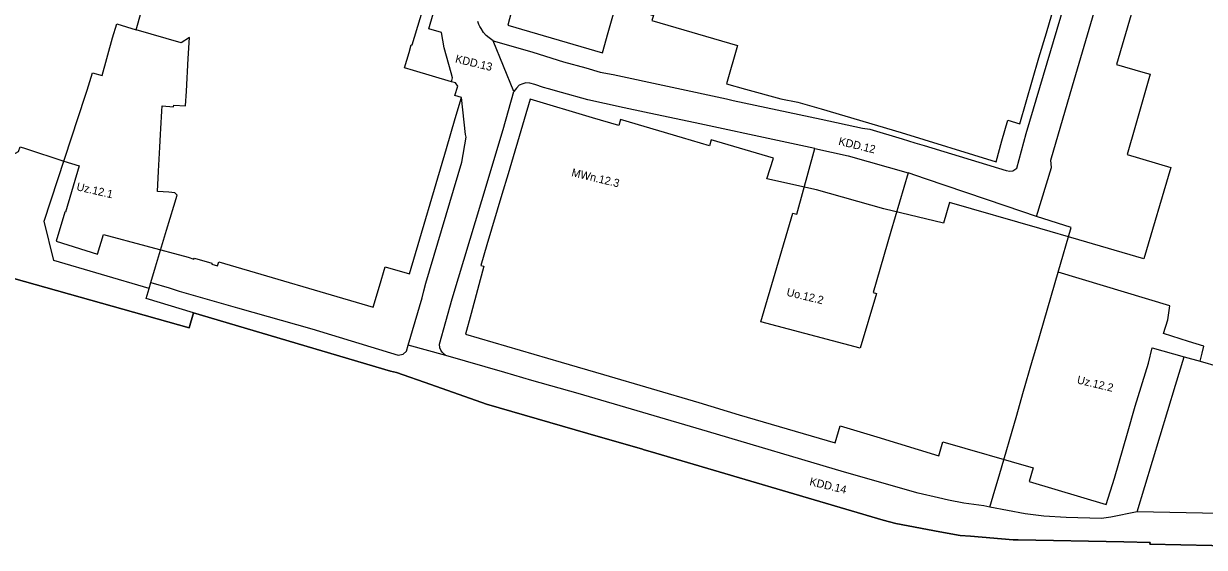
# Model space of a CAD drawing. Extents: x 7429686 to 7432896, y 5547954 to 5550600.
# Drawn here: x 7431434 to 7432024, y 5548197 to 5548459 of the extents above; entities that cross this region are included whole.
import ezdxf

# ---------------------------------------------------------------- set-up
doc = ezdxf.new("R2010")
doc.units = 0
for name, color, linetype in [('granica planu', 7, 'Continuous'), ('linie rozgraniczające', 7, 'Continuous'), ('nieprzekraczalna linia zabudowy', 7, 'Continuous'), ('obowiązująca linia zabudowy', 7, 'Continuous'), ('oznaczenia przeznaczeń', 7, 'Continuous')]:
    doc.layers.add(name, color=color, linetype=linetype)

msp = doc.modelspace()

# ---------------------------------------------------------------- linework, layer by layer
at = {"layer": 'granica planu'}
msp.add_lwpolyline([(7432074.05, 5548197.49), (7431996.63, 5548199.16), (7431996.74, 5548199.92), (7431983.56, 5548200.19), (7431930.9, 5548201.25), (7431928.34, 5548201.3), (7431907.07, 5548203.02), (7431901.88, 5548203.36), (7431891.73, 5548205.25), (7431869.65, 5548209.37), (7431863.43, 5548211.03), (7431747.01, 5548245.4), (7431743.93, 5548246.27), (7431742.66, 5548246.63), (7431722.13, 5548252.46), (7431665.22, 5548269.08), (7431637.34, 5548278.77), (7431620.15, 5548284.73), (7431617.21, 5548285.55), (7431518.77, 5548314.69), (7431516.52, 5548307.08), (7431434.28, 5548330.21), (7431388.06, 5548343.22)], dxfattribs=at)
at = {"layer": 'linie rozgraniczające'}
for points in [[(7431957.96, 5548428.04), (7431981.35, 5548507.31)], [(7431636.27, 5548456.43), (7431648.03, 5548496.92)], [(7431490.15, 5548455.95), (7431500.07, 5548491.36)], [(7431934.9, 5548404.14), (7431960.89, 5548491.66)], [(7431661.32, 5548458.6), (7431660.79, 5548460.09)], [(7431478.2, 5548451.97), (7431480.37, 5548458.9)], [(7431480.37, 5548458.9), (7431490.15, 5548455.95)], [(7431512.58, 5548449.48), (7431490.15, 5548455.95)], [(7431642.63, 5548454.53), (7431636.27, 5548456.43)], [(7431643.98, 5548446.92), (7431642.63, 5548454.53)], [(7431661.85, 5548457.58), (7431661.32, 5548458.6)], [(7431662.53, 5548456.54), (7431661.85, 5548457.58)], [(7431663.6, 5548454.53), (7431662.53, 5548456.54)], [(7431664.98, 5548453.13), (7431663.6, 5548454.53)], [(7431473.07, 5548433.07), (7431478.2, 5548451.97)], [(7431516.72, 5548452.09), (7431512.58, 5548449.48)], [(7431516.05, 5548441.64), (7431516.72, 5548452.09)], [(7431666.42, 5548451.86), (7431664.98, 5548453.13)], [(7431668.5, 5548450.47), (7431666.42, 5548451.86)], [(7431678.87, 5548425.08), (7431668.5, 5548450.47)], [(7431668.5, 5548450.47), (7431670.31, 5548449.95)], [(7431670.31, 5548449.95), (7431688.37, 5548444.77)], [(7431647.5, 5548434.48), (7431643.98, 5548446.92)], [(7431688.37, 5548444.77), (7431703.72, 5548440.02)], [(7431515.18, 5548425.35), (7431516.05, 5548441.64)], [(7431703.72, 5548440.02), (7431714.86, 5548436.88)], [(7431714.86, 5548436.88), (7431722, 5548434.85)], [(7431465.66, 5548425.82), (7431468.21, 5548434.52)], [(7431468.21, 5548434.52), (7431473.07, 5548433.07)], [(7431648.1, 5548431.96), (7431647.5, 5548434.48)], [(7431647.59, 5548430.03), (7431648.1, 5548431.96)], [(7431722, 5548434.85), (7431728.47, 5548433.58)], [(7431728.47, 5548433.58), (7431785.08, 5548421.44)], [(7431464.68, 5548422.82), (7431465.66, 5548425.82)], [(7431514.68, 5548417.92), (7431515.18, 5548425.35)], [(7431649.6, 5548429.38), (7431647.59, 5548430.03)], [(7431649.38, 5548423.12), (7431650.81, 5548427.73)], [(7431650.81, 5548427.73), (7431649.6, 5548429.38)], [(7431673.42, 5548406.14), (7431678.87, 5548425.08)], [(7431680.19, 5548426.73), (7431678.87, 5548425.08)], [(7431681.54, 5548428.25), (7431680.19, 5548426.73)], [(7431683.26, 5548429.02), (7431681.54, 5548428.25)], [(7431684.85, 5548429.41), (7431683.26, 5548429.02)], [(7431686.87, 5548429.31), (7431684.85, 5548429.41)], [(7431689.36, 5548428.64), (7431686.87, 5548429.31)], [(7431693.66, 5548427.08), (7431689.36, 5548428.64)], [(7431696.12, 5548426.51), (7431693.66, 5548427.08)], [(7431702.56, 5548424.56), (7431696.12, 5548426.51)], [(7431715.74, 5548420.98), (7431702.56, 5548424.56)], [(7431947.07, 5548390.83), (7431957.96, 5548428.04)], [(7431444.17, 5548360.33), (7431464.68, 5548422.82)], [(7431652.71, 5548422.08), (7431649.38, 5548423.12)], [(7431654.67, 5548403.73), (7431652.71, 5548422.08)], [(7431724.12, 5548419.07), (7431715.74, 5548420.98)], [(7431733.92, 5548416.95), (7431724.12, 5548419.07)], [(7431785.08, 5548421.44), (7431788.34, 5548420.72)], [(7431788.34, 5548420.72), (7431815.84, 5548414.83)], [(7431502.81, 5548412.54), (7431502.98, 5548415.33)], [(7431502.98, 5548415.33), (7431503.12, 5548417.93)], [(7431503.12, 5548417.93), (7431508.83, 5548417.55)], [(7431508.83, 5548417.55), (7431508.87, 5548418.28)], [(7431508.87, 5548418.28), (7431514.68, 5548417.92)], [(7431744.11, 5548414.79), (7431733.92, 5548416.95)], [(7431771.71, 5548409.04), (7431744.11, 5548414.79)], [(7431815.84, 5548414.83), (7431832.38, 5548411.32)], [(7431502.48, 5548406.58), (7431502.65, 5548409.5)], [(7431502.65, 5548409.5), (7431502.81, 5548412.54)], [(7431810.51, 5548400.66), (7431771.71, 5548409.04)], [(7431832.38, 5548411.32), (7431853.12, 5548406.9)], [(7431853.12, 5548406.9), (7431856.7, 5548406.27)], [(7431502.13, 5548400.5), (7431502.31, 5548403.58)], [(7431502.31, 5548403.58), (7431502.48, 5548406.58)], [(7431652.91, 5548389.89), (7431654.97, 5548402.28)], [(7431654.97, 5548402.28), (7431654.67, 5548403.73)], [(7431662.81, 5548370.74), (7431673.42, 5548406.14)], [(7431856.7, 5548406.27), (7431872.9, 5548401.51)], [(7431872.9, 5548401.51), (7431879.26, 5548399.54)], [(7431930.1, 5548386.8), (7431934.9, 5548404.14)], [(7431501.78, 5548394.31), (7431501.96, 5548397.41)], [(7431501.96, 5548397.41), (7431502.13, 5548400.5)], [(7431829.18, 5548396.6), (7431810.51, 5548400.66)], [(7431820.23, 5548363.95), (7431829.18, 5548396.6)], [(7431829.18, 5548396.6), (7431845.96, 5548392.95)], [(7431879.26, 5548399.54), (7431883.9, 5548398.13)], [(7431883.9, 5548398.13), (7431924.91, 5548385.73)], [(7431501.44, 5548388.35), (7431501.61, 5548391.27)], [(7431501.61, 5548391.27), (7431501.78, 5548394.31)], [(7431634.86, 5548329.45), (7431652.91, 5548389.89)], [(7431845.96, 5548392.95), (7431875.82, 5548384.53)], [(7431947.5, 5548387.1), (7431947.07, 5548390.83)], [(7431501.07, 5548381.89), (7431501.28, 5548385.43)], [(7431501.28, 5548385.43), (7431501.44, 5548388.35)], [(7431875.82, 5548384.53), (7431867.13, 5548355.23)], [(7431884.58, 5548381.54), (7431875.82, 5548384.53)], [(7431924.91, 5548385.73), (7431926.58, 5548385.37)], [(7431926.58, 5548385.37), (7431928.12, 5548385.48)], [(7431928.12, 5548385.48), (7431930.1, 5548386.8)], [(7431940, 5548362.65), (7431947.5, 5548387.1)], [(7431500.7, 5548375.22), (7431500.9, 5548378.62)], [(7431500.9, 5548378.62), (7431501.07, 5548381.89)], [(7431924.86, 5548367.81), (7431884.58, 5548381.54)], [(7431506.48, 5548374.94), (7431500.7, 5548375.22)], [(7431509.5, 5548374.46), (7431506.48, 5548374.94)], [(7431508.93, 5548367.9), (7431510.58, 5548373.39)], [(7431510.58, 5548373.39), (7431509.5, 5548374.46)], [(7431505.29, 5548355.9), (7431508.93, 5548367.9)], [(7431647.95, 5548321.68), (7431662.81, 5548370.74)], [(7431940, 5548362.65), (7431924.86, 5548367.81)], [(7431448.91, 5548340.74), (7431444.17, 5548360.33)], [(7431802.3, 5548310.12), (7431818.15, 5548364.46)], [(7431818.15, 5548364.46), (7431820.23, 5548363.95)], [(7431957.27, 5548357.3), (7431940, 5548362.65)], [(7431499.72, 5548337.5), (7431505.29, 5548355.9)], [(7431867.13, 5548355.23), (7431858.45, 5548324.83)], [(7431950.85, 5548334.94), (7431957.27, 5548357.3)], [(7431388.06, 5548343.22), (7431434.28, 5548330.21), (7431516.52, 5548307.08), (7431518.77, 5548314.69)], [(7431496.54, 5548326.84), (7431448.91, 5548340.74)], [(7431497.42, 5548329.76), (7431499.72, 5548337.5)], [(7431940.12, 5548298.07), (7431950.85, 5548334.94)], [(7432006.6, 5548318.16), (7431950.85, 5548334.94)], [(7431495.02, 5548321.72), (7431496.54, 5548326.84)], [(7431496.54, 5548326.84), (7431497.42, 5548329.76)], [(7431497.42, 5548329.76), (7431506.53, 5548327.04)], [(7431506.53, 5548327.04), (7431511.54, 5548325.51)], [(7431511.54, 5548325.51), (7431540.77, 5548317.07)], [(7431633.08, 5548322.13), (7431633.92, 5548325.58)], [(7431633.92, 5548325.58), (7431634.86, 5548329.45)], [(7431859.96, 5548324.34), (7431851.94, 5548296.96)], [(7431858.45, 5548324.83), (7431859.96, 5548324.34)], [(7431518.77, 5548314.69), (7431495.02, 5548321.72)], [(7431626.05, 5548298.52), (7431633.08, 5548322.13)], [(7431641.74, 5548299.03), (7431647.95, 5548321.68)], [(7431518.77, 5548314.69), (7431617.21, 5548285.55), (7431620.15, 5548284.73), (7431637.34, 5548278.77), (7431665.22, 5548269.08), (7431722.13, 5548252.46), (7431742.66, 5548246.63), (7431743.93, 5548246.27), (7431747.01, 5548245.4), (7431863.43, 5548211.03), (7431869.65, 5548209.37), (7431891.73, 5548205.25), (7431901.88, 5548203.36), (7431907.07, 5548203.02), (7431928.34, 5548201.3), (7431930.9, 5548201.25), (7431983.56, 5548200.19), (7431996.74, 5548199.92), (7431996.63, 5548199.16), (7432074.05, 5548197.49)], [(7431540.77, 5548317.07), (7431577.89, 5548306.6)], [(7432005.67, 5548311.17), (7432006.6, 5548318.16)], [(7431577.89, 5548306.6), (7431621.04, 5548293.51)], [(7431851.94, 5548296.96), (7431802.3, 5548310.12)], [(7432003.5, 5548304.28), (7432005.67, 5548311.17)], [(7432015.98, 5548300.29), (7432003.5, 5548304.28)], [(7431623.58, 5548293.99), (7431625.12, 5548295.51)], [(7431625.12, 5548295.51), (7431626.05, 5548298.52)], [(7431644.87, 5548293.34), (7431626.05, 5548298.52)], [(7431641.85, 5548297.12), (7431641.74, 5548299.03)], [(7431642.38, 5548296.02), (7431641.85, 5548297.12)], [(7431643.05, 5548294.96), (7431642.38, 5548296.02)], [(7431644.87, 5548293.34), (7431643.05, 5548294.96)], [(7431938.06, 5548290.97), (7431940.12, 5548298.07)], [(7432023.57, 5548297.98), (7432015.98, 5548300.29)], [(7432022.69, 5548294.4), (7432023.57, 5548297.98)], [(7431621.04, 5548293.51), (7431623.58, 5548293.99)], [(7431674.38, 5548284.8), (7431644.87, 5548293.34)], [(7431933.19, 5548274.27), (7431938.06, 5548290.97)], [(7432009.39, 5548278.49), (7432013.8, 5548292.64)], [(7432013.8, 5548292.64), (7432021.69, 5548290.39)], [(7432021.69, 5548290.39), (7432022.69, 5548294.4)], [(7432021.69, 5548290.39), (7432049.22, 5548282.54)], [(7431687.8, 5548280.81), (7431674.38, 5548284.8)], [(7431710.89, 5548274.27), (7431687.8, 5548280.81)], [(7431990.34, 5548215.27), (7432009.39, 5548278.49)], [(7431775.63, 5548255.43), (7431710.89, 5548274.27)], [(7431930.08, 5548263.54), (7431933.19, 5548274.27)], [(7431921.25, 5548233.16), (7431930.08, 5548263.54)], [(7431844.08, 5548235.08), (7431775.63, 5548255.43)], [(7431880.93, 5548224.54), (7431844.08, 5548235.08)], [(7431919.19, 5548226.06), (7431921.25, 5548233.16)], [(7431891.04, 5548222.2), (7431880.93, 5548224.54)], [(7431916.63, 5548217.63), (7431919.19, 5548226.06)], [(7431896.06, 5548221.03), (7431891.04, 5548222.2)], [(7431903.74, 5548219.51), (7431896.06, 5548221.03)], [(7431913.7, 5548218.22), (7431903.74, 5548219.51)], [(7431916.63, 5548217.63), (7431913.7, 5548218.22)], [(7431934.32, 5548214.23), (7431916.63, 5548217.63)], [(7431943.57, 5548213), (7431934.32, 5548214.23)], [(7431954.77, 5548212.36), (7431943.57, 5548213)], [(7431972.52, 5548211.9), (7431954.77, 5548212.36)], [(7431977.11, 5548212.6), (7431972.52, 5548211.9)], [(7431990.34, 5548215.27), (7431977.11, 5548212.6)], [(7432055.54, 5548213.88), (7431990.34, 5548215.27)]]:
    msp.add_lwpolyline(points, dxfattribs=at)
at = {"layer": 'nieprzekraczalna linia zabudowy'}
for points in [[(7431345.16, 5548419.82), (7431365.15, 5548414.54), (7431422.01, 5548399.12), (7431423.1, 5548398.77), (7431427.42, 5548397.44), (7431427.23, 5548396.83), (7431428.6, 5548393.61), (7431431.33, 5548395.16), (7431432.06, 5548397.52), (7431434.73, 5548396.59), (7431454.04, 5548390.41)], [(7431997.8, 5548297.21), (7432013.8, 5548292.64)]]:
    msp.add_lwpolyline(points, dxfattribs=at)
at = {"layer": 'obowiązująca linia zabudowy'}
msp.add_line((7431647.59, 5548430.03), (7431628.67, 5548435.65), dxfattribs=at)
for points in [[(7431628.67, 5548435.65), (7431624.22, 5548436.98), (7431626.46, 5548444.68), (7431627.57, 5548448.49), (7431628.08, 5548448.41), (7431639.98, 5548488.13), (7431646.49, 5548510.93), (7431664.93, 5548573.87), (7431658.72, 5548575.66), (7431661.93, 5548587.41)], [(7431922.73, 5548400.45), (7431925.69, 5548410.79), (7431931.72, 5548408.99), (7431941.15, 5548441.9), (7431944.91, 5548454.38), (7431954.48, 5548487.17), (7431949.36, 5548488.59), (7431952.75, 5548500.73), (7431955.79, 5548511.65)], [(7431997.5, 5548498.35), (7431979.97, 5548438.57), (7431993.16, 5548434.77), (7431996.85, 5548433.71), (7431989.47, 5548408.2), (7431985.26, 5548393.68), (7432007.16, 5548387.19), (7431993.68, 5548341.52), (7431961.18, 5548351.01), (7431941.69, 5548356.74), (7431896.45, 5548369.78), (7431893.53, 5548359.39), (7431863.77, 5548366.57), (7431830.11, 5548375.96), (7431805.3, 5548381.48), (7431808.5, 5548391.84), (7431777.38, 5548400.92), (7431776.56, 5548397.98), (7431763.09, 5548401.97), (7431732.06, 5548411.15), (7431731.21, 5548408.15), (7431718.1, 5548412.06), (7431686.95, 5548421.37), (7431683.91, 5548411.12), (7431676.04, 5548384.03), (7431672.85, 5548373.75), (7431665.3, 5548348.6), (7431662.31, 5548338.29), (7431663.9, 5548337.83), (7431657.43, 5548314.27), (7431654.59, 5548303.91)], [(7431678.53, 5548468.36), (7431675.77, 5548458.31), (7431723.14, 5548444.37), (7431726, 5548454.54), (7431729.97, 5548468.66), (7431736.92, 5548466.6), (7431748.64, 5548463.12), (7431747.84, 5548460.58), (7431790.6, 5548448.11), (7431785.1, 5548428.88), (7431794.62, 5548426.27), (7431812.24, 5548421.42), (7431820.72, 5548419.83), (7431832.43, 5548416.4), (7431872.32, 5548404.71), (7431919.77, 5548390.09), (7431922.73, 5548400.45)], [(7431611.7, 5548327.93), (7431614.56, 5548337.65), (7431626.62, 5548334.15), (7431645.21, 5548396.7), (7431649.56, 5548411.67), (7431652.71, 5548422.08)], [(7431454.04, 5548390.41), (7431461.62, 5548387.98), (7431454.84, 5548364.87), (7431454.54, 5548364.96), (7431450.1, 5548350.38), (7431470.82, 5548343.9), (7431473.79, 5548353.67), (7431516.03, 5548342.33)], [(7431516.03, 5548342.33), (7431519, 5548341.35), (7431519.19, 5548341.87), (7431527.94, 5548339.38), (7431527.87, 5548338.94), (7431530.79, 5548338.05), (7431531.39, 5548340.11)], [(7431531.39, 5548340.11), (7431608.58, 5548317.38), (7431611.7, 5548327.93)], [(7431654.59, 5548303.91), (7431702.48, 5548290.03), (7431723.55, 5548283.84), (7431771.22, 5548269.89), (7431791.49, 5548263.66), (7431839.43, 5548249.77), (7431841.96, 5548258.19), (7431860.21, 5548252.65), (7431891.2, 5548243.24), (7431893.22, 5548250.23), (7431938.34, 5548237.26), (7431936.25, 5548230.34), (7431974.84, 5548218.82), (7431978.93, 5548232.13), (7431985.4, 5548254.47), (7431989.37, 5548268.02), (7431995.88, 5548289.49), (7431997.8, 5548297.21)]]:
    msp.add_lwpolyline(points, dxfattribs=at)

# ---------------------------------------------------------------- texts
at = {"layer": 'oznaczenia przeznaczeń'}
for s, rotation, p in [('KDD.13', 346.4891, (7431649.28, 5548439.71)), ('KDD.12', 346.4891, (7431840.77, 5548398.55)), ('MWn.12.3', 346.4891, (7431707.36, 5548382.92)), ('Uz.12.1', 347.06089, (7431460.04, 5548375.87)), ('Uo.12.2', 346.4891, (7431814.82, 5548323.23)), ('Uz.12.2', 346.4891, (7431959.94, 5548279.43)), ('KDD.14', 346.4891, (7431826.3, 5548228.61))]:
    msp.add_text(s, height=4, rotation=rotation, dxfattribs=at).set_placement(p)

doc.saveas('drawing.dxf')
